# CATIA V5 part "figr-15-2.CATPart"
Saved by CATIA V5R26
Part number: Part1
Bounding box of the stored display mesh (mm): x -101.427 to 121.258, y -118.645 to 66.112, z 0 to 1
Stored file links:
  D:\_Deepak\CATIA\CATIA V5-6R2016_Deepak\Resources\Part files\Partfiles\c15_catia_v5_6r2016_prt\figr-15-2.CATPart
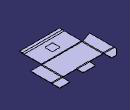
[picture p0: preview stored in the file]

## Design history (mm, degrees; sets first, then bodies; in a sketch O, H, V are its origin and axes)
SheetMetalParameters1: Thickness 1, BendRadius 2, KFactor 0.400515 {= log(min(100,max(20*SheetMetalParameters1.BendRadius,SheetMetalParameters1.Thickness)/SheetMetalParameters1.Thickness))/log(100)/2}, ReliefRadialLength 1, ReliefAxialLength 2, WallPerLength 50, MinimumBendRadius 0
Body1 (main body)
  Sketch1 on xy-plane, origin (0, 0, 0), H (1, 0, 0), V (0, 1, 0)
    line L1 (-62.6567, 37.3409) -> (82.4875, 37.3409)
    line L2 (82.4875, 37.3409) -> (82.4875, -38.1848)
    line L3 (82.4875, -38.1848) -> (-62.6567, -38.1848)
    line L4 (-62.6567, -38.1848) -> (-62.6567, 37.3409)
    horizontal: L1 H, L3 H
    vertical: L2 V, L4 V
  Wall1: Thickness 1, Profile Sketch1, OffsetValue 0
  d_NewWallOnEdge1: NewWallOnEdge_Length 25, KFacteur 0.400515 {= log(min(100,max(20*d_NewWallOnEdge1.Radius,SheetMetalParameters1.Thickness)/SheetMetalParameters1.Thickness))/log(100)/2}, NewWallOnEdge_HeightLimitOffset 0, NewWallOnEdge_WidthOffset1 -50, NewWallOnEdge_WidthOffset2 -50, NewWallOnEdge_Angle 90, NewWallOnEdge_BendRadiusValue 2 {= SheetMetalParameters1.BendRadius}, NewWallOnEdge_BendTable SheetMetalParameters1, NewWallOnEdge_Edge edge [face of Wall1 | face of Wall1], NewWallOnEdge_GapValue 0
  d_NewWallOnEdge2: NewWallOnEdge_Length 40, NewWallOnEdge_HeightLimitOffset 0, NewWallOnEdge_WidthOffset1 0, NewWallOnEdge_WidthOffset2 0, NewWallOnEdge_Angle 90, NewWallOnEdge_BendRadiusValue 2 {= SheetMetalParameters1.BendRadius}, NewWallOnEdge_BendTable SheetMetalParameters1, NewWallOnEdge_Edge edge [face of Wall1 | face of Wall1], NewWallOnEdge_GapValue 0, KFacteur 0.400515 {= log(min(100,max(20*d_NewWallOnEdge2.Radius,SheetMetalParameters1.Thickness)/SheetMetalParameters1.Thickness))/log(100)/2}
  d_NewWallOnEdge3: NewWallOnEdge_Length 30, NewWallOnEdge_HeightLimitOffset 0, NewWallOnEdge_WidthOffset1 0, NewWallOnEdge_WidthOffset2 0, NewWallOnEdge_Angle 90, NewWallOnEdge_BendRadiusValue 2 {= SheetMetalParameters1.BendRadius}, NewWallOnEdge_BendTable SheetMetalParameters1, NewWallOnEdge_Edge edge [face of d_NewWallOnEdge2 | face of d_NewWallOnEdge2], NewWallOnEdge_GapValue 0, KFacteur 0.400515 {= log(min(100,max(20*d_NewWallOnEdge3.Radius,SheetMetalParameters1.Thickness)/SheetMetalParameters1.Thickness))/log(100)/2}
  d_NewWallOnEdge4: NewWallOnEdge_Length 60, NewWallOnEdge_HeightLimitOffset 0, NewWallOnEdge_WidthOffset1 0, NewWallOnEdge_WidthOffset2 0, NewWallOnEdge_Angle 110, NewWallOnEdge_BendRadiusValue 2 {= SheetMetalParameters1.BendRadius}, NewWallOnEdge_BendTable SheetMetalParameters1, NewWallOnEdge_Edge edge [face of Wall1 | face of Wall1], NewWallOnEdge_GapValue 0, KFacteur 0.400515 {= log(min(100,max(20*d_NewWallOnEdge4.Radius,SheetMetalParameters1.Thickness)/SheetMetalParameters1.Thickness))/log(100)/2}
  Flange1: Guide edge [face of d_NewWallOnEdge4 | face of d_NewWallOnEdge4], Angle 90, KFacteur 0.400515 {= log(min(100,max(20*Flange1.Radius,SheetMetalParameters1.Thickness)/SheetMetalParameters1.Thickness))/log(100)/2}, Length 10, Radius 2 {= SheetMetalParameters1.BendRadius}
  d_NewWallOnEdge5: NewWallOnEdge_Length 40, NewWallOnEdge_HeightLimitOffset 0, NewWallOnEdge_WidthOffset1 0, NewWallOnEdge_WidthOffset2 -2, NewWallOnEdge_Angle 90, NewWallOnEdge_WidthLimit2 face of d_NewWallOnEdge4, NewWallOnEdge_WithBend true, NewWallOnEdge_BendRadiusValue 2 {= SheetMetalParameters1.BendRadius}, NewWallOnEdge_BendTable SheetMetalParameters1, NewWallOnEdge_Edge edge [face of Wall1 | face of Wall1], NewWallOnEdge_GapValue 0, KFacteur 0.400515 {= log(min(100,max(20*d_NewWallOnEdge5.Radius,SheetMetalParameters1.Thickness)/SheetMetalParameters1.Thickness))/log(100)/2}
  d_NewWallOnEdge6: NewWallOnEdge_Length 30, NewWallOnEdge_HeightLimitOffset 0, NewWallOnEdge_WidthOffset1 0, NewWallOnEdge_WidthOffset2 0, NewWallOnEdge_Angle 90, NewWallOnEdge_BendRadiusValue 2 {= SheetMetalParameters1.BendRadius}, NewWallOnEdge_BendTable SheetMetalParameters1, NewWallOnEdge_Edge edge [face of d_NewWallOnEdge5 | face of d_NewWallOnEdge5], NewWallOnEdge_GapValue 0, KFacteur 0.400515 {= log(min(100,max(20*d_NewWallOnEdge6.Radius,SheetMetalParameters1.Thickness)/SheetMetalParameters1.Thickness))/log(100)/2}
  Chamfer1: ChamferAngle 45, ChamferLength1 20, ChamferLength2 0.5, ChamferPropagation 1, ChamferReverse false, ChamferType 1, CornerChamferEdges edge [face of d_NewWallOnEdge6 | face of d_NewWallOnEdge6]
  Corner1: CornerChamferEdges (edge [face of d_NewWallOnEdge1 | face of d_NewWallOnEdge1]; edge [face of d_NewWallOnEdge1 | face of d_NewWallOnEdge1]), CornerRadius 3
  Sketch2 on face of d_NewWallOnEdge4, origin (8.9154, -38.1848, 1), H (1, 0, 0), V (0, -0.342, 0.9397)
    line L1 (-12.2908, 45.4061) -> (12.3784, 45.4061)
    line L2 (12.3784, 45.4061) -> (12.3784, 21.719)
    line L3 (12.3784, 21.719) -> (-12.2908, 21.719)
    line L4 (-12.2908, 21.719) -> (-12.2908, 45.4061)
    horizontal: L1 H, L3 H
    vertical: L2 V, L4 V
  d_Stamp1: Stamp_FilletRadius 1, NewRoot_AttribNormalisation "No Standard", Stamp_IntersectFilletRadius 2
